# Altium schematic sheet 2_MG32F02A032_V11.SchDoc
size 381 x 241 mm
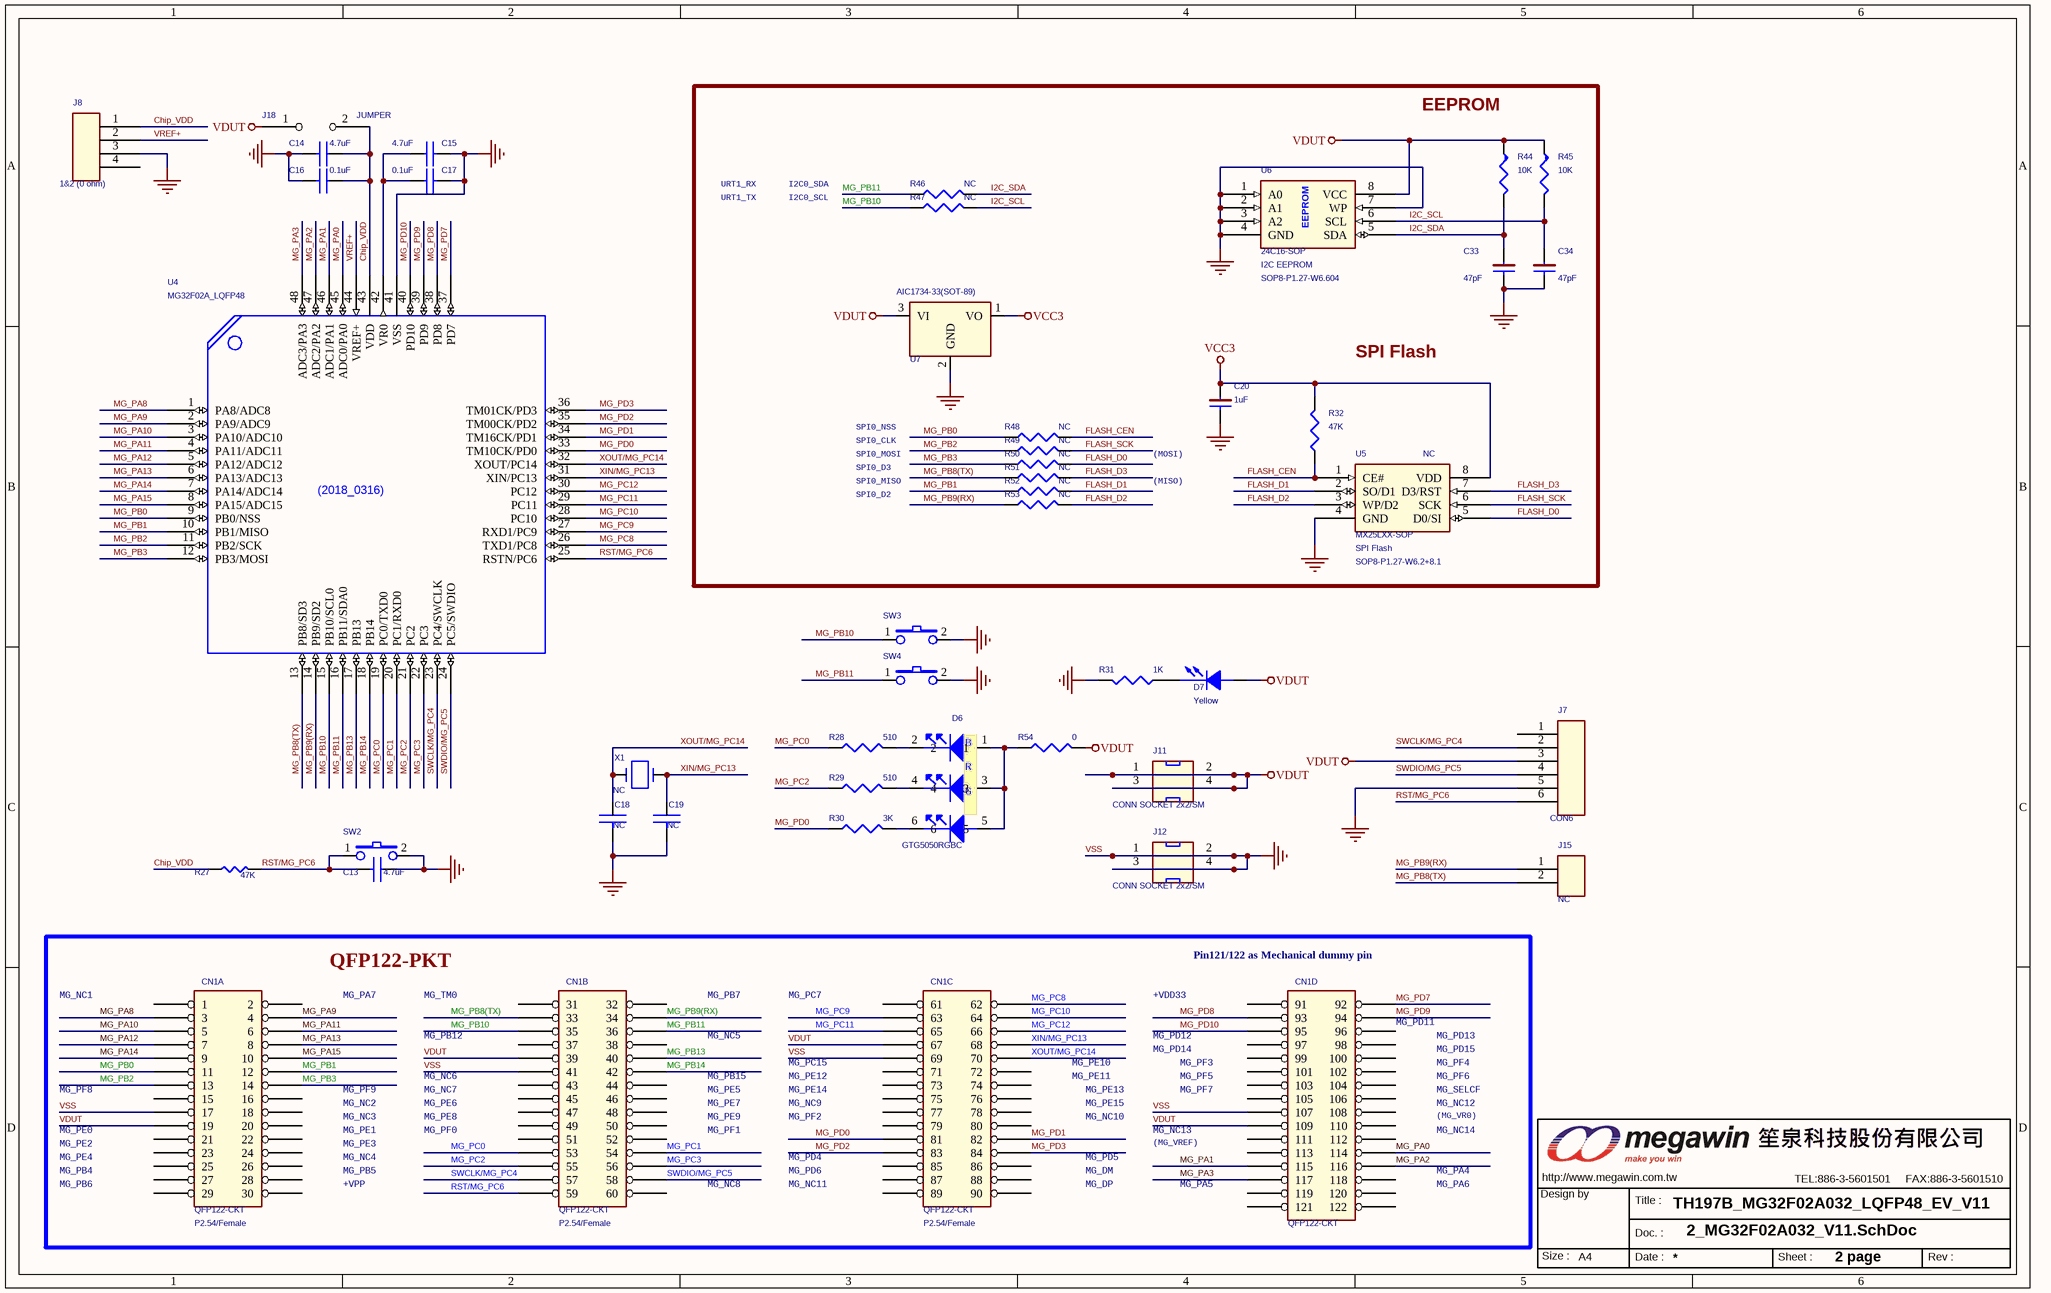
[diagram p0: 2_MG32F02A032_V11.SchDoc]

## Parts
C13  4.7uF  [0805C]
C14  4.7uF  [0805C]
C15  4.7uF  [0805C]
C16  0.1uF  [0603C]
C17  0.1uF  [0603C]
C18  NC  [0603C]
C19  NC  [0603C]
C20  1uF  [0603C]
C33  47pF  [0603C]
C34  47pF  [0603C]
CN1  QFP122-CKT  Package: P2.54/Female  [QFP122-P2.54-CKT]  (parts A,B,C,D of 4)
D6  GTG5050RGBC  [LED6P_RGB_SMD_50X50]
D7  Yellow  [0805D]
J7  CON6  [PS6P254]
J8  1&2 (0 ohm)  [PS4P254]
J11  CONN SOCKET 2x2/SM  [PS2X2P254]
J12  CONN SOCKET 2x2/SM  [PS2X2P254]
J15  NC  [PS2P254]
J18  JUMPER  [PS2P254]
MW1  OrgAddr3: TEL:886-3-5601501     FAX:886-3-5601510  [MEGAWIN_3.4]  (hidden comment: MW-A4)  (graphical)
R27  47K  [0603R]
R28  510  [0603R]
R29  510  [0603R]
R30  3K  [0603R]
R31  1K  [0603R]
R32  47K  [0603R]
R44  10K  [0603R]
R45  10K  [0603R]
R46  NC  [0603R]
R47  NC  [0603R]
R48  NC  [0603R]
R49  NC  [0603R]
R50  NC  [0603R]
R51  NC  [0603R]
R52  NC  [0603R]
R53  NC  [0603R]
R54  0  [PS2p254+0603]
SW2  SW TACT-SPST  [SW_T_2P]  (value not drawn)
SW3  SW TACT-SPST  [SW_T_2P]  (value not drawn)
SW4  SW TACT-SPST  [SW_T_2P]  (value not drawn)
U4  MG32F02A_LQFP48  [LQFP48_7X7_050]
U5  MX25LXX-SOP  Function: SPI Flash  Assembly: NC  Package: SOP8-P1.27-W6.2+8.1  [SO8_208P127]
U6  24C16-SOP  Function: I2C EEPROM  Package: SOP8-P1.27-W6.604  [SO8_150P127]
U7  AIC1734-33(SOT-89)  [SOT89]
X1  NC  [X49U]

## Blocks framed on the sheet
QFP122-PKT: CN1

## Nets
VCC3: C20.1 R32.2 U5.8(VDD) U7.1(VO)
VDUT: CN1.19 CN1.39 CN1.67 CN1.109 D7.1(ANODE) J7.3 J11.1 J11.2 J11.3 J11.4 J18.1 R44.1 R45.1 R54.2 U6.8(VCC) U7.3(VI)
VSS: C13.1 C14.2 C15.2 C16.2 C17.2 C18.2 C19.2 C20.2 C33.2 C34.2 CN1.17 CN1.41 CN1.69 CN1.107 J7.5 J8.3 J12.1 J12.2 J12.3 J12.4 R31.1 SW2.2 SW3.2 SW4.2 U4.41(VSS) U5.4(GND) U6.1(A0) U6.2(A1) U6.3(A2) U6.4(GND) U6.7(WP) U7.2(GND)  [also labelled GND_POWER]
Chip_VDD: C14.1 C16.1 J8.1 J18.2 R27.1 U4.43(VDD)
FLASH_CEN: R32.1 R48.2 U5.1(CE#)
FLASH_D0: R50.2 U5.5(D0/SI)
FLASH_D1: R52.2 U5.2(SO/D1)
FLASH_D2: R53.2 U5.3(WP/D2)
FLASH_D3: R51.2 U5.7(D3/RST)
FLASH_SCK: R49.2 U5.6(SCK)
I2C_SCL: C34.1 R45.2 R47.2 U6.6(SCL)
I2C_SDA: C33.1 R44.2 R46.2 U6.5(SDA)
MG_PA0: CN1.114 U4.45(ADC0/PA0)
MG_PA1: CN1.115 U4.46(ADC1/PA1)
MG_PA2: CN1.116 U4.47(ADC2/PA2)
MG_PA3: CN1.117 U4.48(ADC3/PA3)
MG_PA8: CN1.3 U4.1(PA8/ADC8)
MG_PA9: CN1.4 U4.2(PA9/ADC9)
MG_PA10: CN1.5 U4.3(PA10/ADC10)
MG_PA11: CN1.6 U4.4(PA11/ADC11)
MG_PA12: CN1.7 U4.5(PA12/ADC12)
MG_PA13: CN1.8 U4.6(PA13/ADC13)
MG_PA14: CN1.9 U4.7(PA14/ADC14)
MG_PA15: CN1.10 U4.8(PA15/ADC15)
MG_PB0: CN1.11 R48.1 U4.9(PB0/NSS)
MG_PB1: CN1.12 R52.1 U4.10(PB1/MISO)
MG_PB2: CN1.13 R49.1 U4.11(PB2/SCK)
MG_PB3: CN1.14 R50.1 U4.12(PB3/MOSI)
MG_PB8(TX): CN1.33 J15.2 R51.1 U4.13(PB8/SD3)
MG_PB9(RX): CN1.34 J15.1 R53.1 U4.14(PB9/SD2)
MG_PB10: CN1.35 R47.1 SW3.1 U4.15(PB10/SCL0)
MG_PB11: CN1.36 R46.1 SW4.1 U4.16(PB11/SDA0)
MG_PB13: CN1.40 U4.17(PB13)
MG_PB14: CN1.42 U4.18(PB14)
MG_PC0: CN1.53 R28.1 U4.19(PC0/TXD0)
MG_PC1: CN1.54 U4.20(PC1/RXD0)
MG_PC2: CN1.55 R29.1 U4.21(PC2)
MG_PC3: CN1.56 U4.22(PC3)
MG_PC8: CN1.62 U4.26(TXD1/PC8)
MG_PC9: CN1.63 U4.27(RXD1/PC9)
MG_PC10: CN1.64 U4.28(PC10)
MG_PC11: CN1.65 U4.29(PC11)
MG_PC12: CN1.66 U4.30(PC12)
MG_PD0: CN1.81 R30.1 U4.33(TM10CK/PD0)
MG_PD1: CN1.82 U4.34(TM16CK/PD1)
MG_PD2: CN1.83 U4.35(TM00CK/PD2)
MG_PD3: CN1.84 U4.36(TM01CK/PD3)
MG_PD7: CN1.92 U4.37(PD7)
MG_PD8: CN1.93 U4.38(PD8)
MG_PD9: CN1.94 U4.39(PD9)
MG_PD10: CN1.95 U4.40(PD10)
RST/MG_PC6: C13.2 CN1.59 J7.6 R27.2 SW2.1 U4.25(RSTN/PC6)
SWCLK/MG_PC4: CN1.57 J7.2 U4.23(PC4/SWCLK)
SWDIO/MG_PC5: CN1.58 J7.4 U4.24(PC5/SWDIO)
VREF+: J8.2 U4.44(VREF+)
XIN/MG_PC13: C19.1 CN1.68 U4.31(XIN/PC13) X1.2
XOUT/MG_PC14: C18.1 CN1.70 U4.32(XOUT/PC14) X1.1
NetC15_1: C15.1 C17.1 U4.42(VR0)
NetD6_1: D6.1 D6.3 D6.5 R54.1
NetD6_2: D6.2 R28.2
NetD6_4: D6.4 R29.2
NetD6_6: D6.6 R30.2
NetD7_2: D7.2(CATHODE) R31.2

Not connected (* = marked no-connect by the designer): CN1 1 2 15 16 18 20 21 22 23 24 25 26 27 28 29 30 31 32 37 38 43 44 45 46 47 48 49 50 51 52 60 61 71 72 73 74 75 76 77 78 79 80 85 86 87 88 89 90 91 96 97 98 99 100 101 102 103 104 105 106 108 110 111 112 113 118 119 120 121 122; J7 1; J8 4

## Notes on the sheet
- (near R44) EEPROM
- URT1_TX
- URT1_RX
- I2C0_SDA
- I2C0_SCL
- SPI Flash
- SPI0_NSS
- SPI0_CLK
- SPI0_MOSI
- SPI0_MISO
- SPI0_D3
- SPI0_D2
- (MOSI)
- (MISO)
- (near CN1) Pin121/122 as Mechanical dummy pin
- MG_NC1
- MG_PA7
- MG_TM0
- MG_PB12
- MG_NC5
- MG_PB7
- MG_PC7
- +VDD33
- MG_PD12
- (near CN1) MG_PD11
- MG_PD13
- MG_PF8
- MG_PF9
- MG_NC2
- MG_NC6
- MG_NC7
- MG_PE6
- MG_PE5
- MG_PE7
- MG_PB15
- MG_PC15
- MG_NC9
- MG_PE12
- MG_PE14
- MG_PE11
- MG_PE10
- MG_PE13
- MG_PE15
- MG_PD14
- MG_PF3
- MG_PF5
- MG_PF7
- MG_NC12
- MG_PF4
- MG_PF6
- MG_SELCF
- MG_PD15
- MG_PE4
- MG_PE0
- MG_PE2
- MG_PB4
- MG_NC3
- MG_NC4
- MG_PE1
- MG_PE3
- MG_PB5
- MG_PF0
- MG_PE8
- MG_PF1
- MG_PE9
- MG_PF2
- MG_PD4
- MG_PD6
- MG_DM
- MG_NC10
- MG_PD5
- MG_NC13
- (MG_VREF)
- MG_NC14
- (MG_VR0)
- MG_PA4
- MG_PB6
- +VPP
- MG_NC8
- MG_NC11
- MG_DP
- MG_PA5
- MG_PA6
- TH197B_MG32F02A032_LQFP48_EV_V11
- 2 page

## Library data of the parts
C13-C17 = CAP NP_Dup1
C18 C19 = C NP_Dup1
C20 C33 C34 = CAP-NP
D6 = LED_GTG5050RGBC
D7 = LED
J7 = CON6_Dup1
J8 = CON4
J15 = CON2
MW1 = MW_A4_2
R27 = R_Dup4
R28-R32 R46-R54 = R_Dup5
R44 R45 = R: 2ND PART FIELD: SMD_0805
U4 = IC-MG32F02A032-LQFP48: Designator: A; OriginalSymbolOrigin: (0,0); SWAP_INFO: (S1+S2); SPLIT_INST: TRUE
U5 = ICM-25LXX
U6 = ICM-24CXX: 1ST PART FIELD: OSD Record Buffer; 2ND PART FIELD: SOP_8PIN
U7 = AIC1722-33
X1 = CRYSTAL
